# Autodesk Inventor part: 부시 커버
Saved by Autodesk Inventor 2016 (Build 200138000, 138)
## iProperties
Created: 2024-08
Part Number: 부시 커버
Material: 일반
Document SubType Name: Modeling
Designer: pc-2
Density: 1 g/cm^3
Appearance: 기본값
Author: jhkim
Sending System: Autodesk Inventor 2025
Preprocessor: ST-DEVELOPER v20
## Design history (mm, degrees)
node "부시 커버1"
node "솔리드2"
node "솔리드1"
